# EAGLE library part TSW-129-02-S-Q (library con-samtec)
THROUGH-HOLE .025" SQ POST HEADER Source: Samtec TSW.pdf
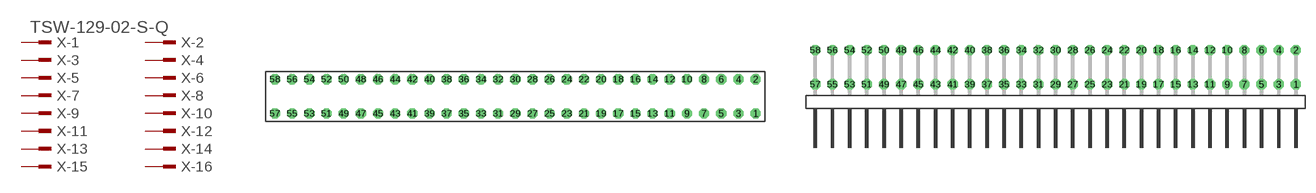
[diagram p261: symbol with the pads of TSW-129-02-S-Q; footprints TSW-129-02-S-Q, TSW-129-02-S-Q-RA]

Designator prefix X; gates -1=MPINV -2=MPIN -3=MPIN -4=MPIN -5=MPIN -6=MPIN -7=MPIN -8=MPIN -9=MPIN -10=MPIN -11=MPIN -12=MPIN -13=MPIN -14=MPIN -15=MPIN -16=MPIN -17=MPIN -18=MPIN -19=MPIN -20=MPIN -21=MPIN -22=MPIN -23=MPIN -24=MPIN -25=MPIN -26=MPIN -27=MPIN -28=MPIN -29=MPIN -30=MPIN -31=MPIN -32=MPIN -33=MPIN -34=MPIN -35=MPIN -36=MPIN -37=MPIN -38=MPIN -39=MPIN -40=MPIN -41=MPIN -42=MPIN -43=MPIN -44=MPIN -45=MPIN -46=MPIN -47=MPIN -48=MPIN -49=MPIN -50=MPIN -51=MPIN -52=MPIN -53=MPIN -54=MPIN -55=MPIN -56=MPIN -57=MPIN -58=MPIN

## TSW-129-02-S-Q (OC_FARNELL: unknown; OC_NEWARK: unknown)  [TSW-129-02-S-Q]
1  -1:1  pas
2  -2:1  pas
3  -3:1  pas
4  -4:1  pas
5  -5:1  pas
6  -6:1  pas
7  -7:1  pas
8  -8:1  pas
9  -9:1  pas
10  -10:1  pas
11  -11:1  pas
12  -12:1  pas
13  -13:1  pas
14  -14:1  pas
15  -15:1  pas
16  -16:1  pas
17  -17:1  pas
18  -18:1  pas
19  -19:1  pas
20  -20:1  pas
21  -21:1  pas
22  -22:1  pas
23  -23:1  pas
24  -24:1  pas
25  -25:1  pas
26  -26:1  pas
27  -27:1  pas
28  -28:1  pas
29  -29:1  pas
30  -30:1  pas
31  -31:1  pas
32  -32:1  pas
33  -33:1  pas
34  -34:1  pas
35  -35:1  pas
36  -36:1  pas
37  -37:1  pas
38  -38:1  pas
39  -39:1  pas
40  -40:1  pas
41  -41:1  pas
42  -42:1  pas
43  -43:1  pas
44  -44:1  pas
45  -45:1  pas
46  -46:1  pas
47  -47:1  pas
48  -48:1  pas
49  -49:1  pas
50  -50:1  pas
51  -51:1  pas
52  -52:1  pas
53  -53:1  pas
54  -54:1  pas
55  -55:1  pas
56  -56:1  pas
57  -57:1  pas
58  -58:1  pas

## TSW-129-02-S-Q-RA (OC_FARNELL: unknown; OC_NEWARK: unknown)  [TSW-129-02-S-Q-RA]
Pads as for TSW-129-02-S-Q

## Footprint TSW-129-02-S-Q (pad centres in mm)
THROUGH-HOLE .025" SQ POST HEADER Source: Samtec TSW.pdf
drill 1 pad 1.5 octagon: 1 35.56,-2.54; 2 35.56,2.54; 3 33.02,-2.54; 4 33.02,2.54; 5 30.48,-2.54; 6 30.48,2.54; 7 27.94,-2.54; 8 27.94,2.54; 9 25.4,-2.54; 10 25.4,2.54; 11 22.86,-2.54; 12 22.86,2.54; 13 20.32,-2.54; 14 20.32,2.54; 15 17.78,-2.54; 16 17.78,2.54; 17 15.24,-2.54; 18 15.24,2.54; 19 12.7,-2.54; 20 12.7,2.54; 21 10.16,-2.54; 22 10.16,2.54; 23 7.62,-2.54; 24 7.62,2.54; 25 5.08,-2.54; 26 5.08,2.54; 27 2.54,-2.54; 28 2.54,2.54; 29 0,-2.54; 30 0,2.54; 31 -2.54,-2.54; 32 -2.54,2.54; 33 -5.08,-2.54; 34 -5.08,2.54; 35 -7.62,-2.54; 36 -7.62,2.54; 37 -10.16,-2.54; 38 -10.16,2.54; 39 -12.7,-2.54; 40 -12.7,2.54; 41 -15.24,-2.54; 42 -15.24,2.54; 43 -17.78,-2.54; 44 -17.78,2.54; 45 -20.32,-2.54; 46 -20.32,2.54; 47 -22.86,-2.54; 48 -22.86,2.54; 49 -25.4,-2.54; 50 -25.4,2.54; 51 -27.94,-2.54; 52 -27.94,2.54; 53 -30.48,-2.54; 54 -30.48,2.54; 55 -33.02,-2.54; 56 -33.02,2.54; 57 -35.56,-2.54; 58 -35.56,2.54

## Footprint TSW-129-02-S-Q-RA (pad centres in mm)
THROUGH-HOLE .025" SQ POST HEADER Source: Samtec TSW.pdf
drill 1 pad 1.5 octagon: 1 35.56,1.524; 2 35.56,6.604; 3 33.02,1.524; 4 33.02,6.604; 5 30.48,1.524; 6 30.48,6.604; 7 27.94,1.524; 8 27.94,6.604; 9 25.4,1.524; 10 25.4,6.604; 11 22.86,1.524; 12 22.86,6.604; 13 20.32,1.524; 14 20.32,6.604; 15 17.78,1.524; 16 17.78,6.604; 17 15.24,1.524; 18 15.24,6.604; 19 12.7,1.524; 20 12.7,6.604; 21 10.16,1.524; 22 10.16,6.604; 23 7.62,1.524; 24 7.62,6.604; 25 5.08,1.524; 26 5.08,6.604; 27 2.54,1.524; 28 2.54,6.604; 29 0,1.524; 30 0,6.604; 31 -2.54,1.524; 32 -2.54,6.604; 33 -5.08,1.524; 34 -5.08,6.604; 35 -7.62,1.524; 36 -7.62,6.604; 37 -10.16,1.524; 38 -10.16,6.604; 39 -12.7,1.524; 40 -12.7,6.604; 41 -15.24,1.524; 42 -15.24,6.604; 43 -17.78,1.524; 44 -17.78,6.604; 45 -20.32,1.524; 46 -20.32,6.604; 47 -22.86,1.524; 48 -22.86,6.604; 49 -25.4,1.524; 50 -25.4,6.604; 51 -27.94,1.524; 52 -27.94,6.604; 53 -30.48,1.524; 54 -30.48,6.604; 55 -33.02,1.524; 56 -33.02,6.604; 57 -35.56,1.524; 58 -35.56,6.604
